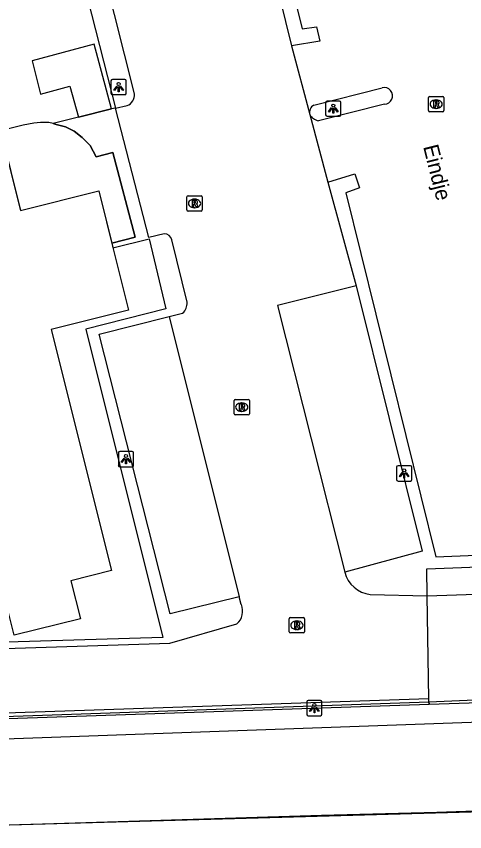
# Model space of a CAD drawing. Extents: x 160806 to 161707, y 383697 to 384148.
# Drawn here: x 160956.3 to 160985.6, y 383697.5 to 383750.7 of the extents above; entities that cross this region are included whole.
import ezdxf

# ---------------------------------------------------------------- set-up
doc = ezdxf.new("R2010")
doc.units = 0
for name, color, linetype in [('IMGEO_Dek', 7, 'Continuous'), ('IMGEO_Hek', 7, 'Continuous'), ('IMGEO_Lichtpunt', 7, 'Continuous'), ('IMGEO_Muur', 7, 'Continuous'), ('IMGEO_Openbare_ruimte_label', 7, 'Continuous'), ('IMGEO_Pand', 7, 'Continuous'), ('IMGEO_Pand_overbouw', 7, 'Continuous'), ('IMGEO_Parkeervlak_gesloten', 7, 'Continuous'), ('IMGEO_Parkeervlak_open', 7, 'Continuous'), ('IMGEO_Rijbaan_lokaal_gesloten', 7, 'Continuous'), ('IMGEO_Rioolput', 7, 'Continuous'), ('IMGEO_Spoorbaan_halfverhard', 7, 'Continuous'), ('IMGEO_Struiken', 7, 'Continuous'), ('IMGEO_Voetpad_gesloten', 7, 'Continuous'), ('IMGEO_Voetpad_op_trap', 7, 'Continuous')]:
    doc.layers.add(name, color=color, linetype=linetype)

msp = doc.modelspace()

# ---------------------------------------------------------------- linework, layer by layer
at = {"layer": 'IMGEO_Dek'}
for points in [[(160918.048, 383703.574), (160983.268, 383705.804), (160983.265, 383705.961), (161017.778, 383707.453), (161017.526, 383714.059), (161017.47, 383715.97), (161042.245, 383716.936), (161047.689, 383726.041), (161047.527, 383726.542), (161047.162, 383727.994), (161034.181, 383780.096)], [(160959.395, 383758.125), (160962.801, 383744.714), (160962.544, 383744.668), (160960.397, 383744.126), (160958.73, 383743.717), (160958.926, 383743.665), (160959.552, 383743.495), (160960.1, 383743.212), (160960.626, 383742.816), (160961.142, 383742.274), (160961.54, 383741.548), (160962.624, 383741.824), (160964.085, 383736.287), (160962.561, 383735.906), (160962.637, 383735.601), (160965.01, 383736.193), (160966.097, 383731.614), (160960.872, 383730.295), (160965.894, 383710.159), (160949.913, 383709.678)]]:
    msp.add_lwpolyline(points, dxfattribs=at)
at = {"layer": 'IMGEO_Hek'}
msp.add_lwpolyline([(161084.555, 383704.866), (161082.059, 383704.545), (161077.717, 383703.87), (161074.945, 383703.576), (161073.852, 383703.453), (161066.359, 383702.75), (161053.876, 383701.607), (161046.412, 383701.035), (161041.411, 383700.754), (161031.392, 383700.349), (161013.875, 383699.768), (161008.19, 383699.597), (160996.33, 383699.168), (160983.78, 383698.726), (160976.256, 383698.527), (160958.785, 383697.993), (160951.307, 383697.771), (160943.792, 383697.709), (160938.784, 383697.68), (160932.094, 383697.764)], dxfattribs=at)
at = {"layer": 'IMGEO_Lichtpunt'}
for p, q in [((160963.413, 383746.6), (160962.605, 383746.6)), ((160963.413, 383746.6), (160962.605, 383746.6)), ((160962.511, 383746.505), (160962.511, 383745.698)), ((160962.511, 383746.505), (160962.511, 383745.698)), ((160963.507, 383745.698), (160963.507, 383746.505)), ((160963.507, 383745.698), (160963.507, 383746.505)), ((160962.605, 383745.604), (160963.413, 383745.604)), ((160962.605, 383745.604), (160963.413, 383745.604)), ((160976.521, 383745.093), (160976.521, 383744.286)), ((160976.521, 383745.093), (160976.521, 383744.286)), ((160977.423, 383745.188), (160976.615, 383745.188)), ((160977.423, 383745.188), (160976.615, 383745.188)), ((160977.517, 383744.286), (160977.517, 383745.093)), ((160977.517, 383744.286), (160977.517, 383745.093)), ((160976.615, 383744.192), (160977.423, 383744.192)), ((160976.615, 383744.192), (160977.423, 383744.192)), ((160962.99, 383722.203), (160962.99, 383721.396)), ((160962.99, 383722.203), (160962.99, 383721.396)), ((160963.892, 383722.298), (160963.084, 383722.298)), ((160963.892, 383722.298), (160963.084, 383722.298)), ((160963.986, 383721.396), (160963.986, 383722.203)), ((160963.986, 383721.396), (160963.986, 383722.203)), ((160963.084, 383721.302), (160963.892, 383721.302)), ((160963.084, 383721.302), (160963.892, 383721.302)), ((160981.148, 383721.27), (160981.148, 383720.463)), ((160981.148, 383721.27), (160981.148, 383720.463)), ((160982.05, 383721.365), (160981.242, 383721.365)), ((160982.05, 383721.365), (160981.242, 383721.365)), ((160982.144, 383720.463), (160982.144, 383721.27)), ((160982.144, 383720.463), (160982.144, 383721.27)), ((160981.242, 383720.369), (160982.05, 383720.369)), ((160981.242, 383720.369), (160982.05, 383720.369)), ((160975.284, 383705.946), (160975.284, 383705.139)), ((160975.284, 383705.946), (160975.284, 383705.139)), ((160976.186, 383706.041), (160975.378, 383706.041)), ((160976.186, 383706.041), (160975.378, 383706.041)), ((160976.28, 383705.139), (160976.28, 383705.946)), ((160976.28, 383705.139), (160976.28, 383705.946)), ((160975.378, 383705.045), (160976.186, 383705.045)), ((160975.378, 383705.045), (160976.186, 383705.045))]:
    msp.add_line(p, q, dxfattribs=at)
for points in [[(160962.885, 383746.169), (160962.924, 383746.141), (160962.736, 383745.879), (160962.698, 383745.906), (160962.885, 383746.169)], [(160962.987, 383746.121), (160963.034, 383746.121), (160963.034, 383745.799), (160962.987, 383745.799), (160962.987, 383746.121)], [(160963.097, 383746.141), (160963.135, 383746.168), (160963.322, 383745.906), (160963.283, 383745.878), (160963.097, 383746.141)], [(160976.895, 383744.757), (160976.934, 383744.729), (160976.746, 383744.467), (160976.708, 383744.494), (160976.895, 383744.757)], [(160976.997, 383744.709), (160977.044, 383744.709), (160977.044, 383744.387), (160976.997, 383744.387), (160976.997, 383744.709)], [(160977.107, 383744.729), (160977.145, 383744.756), (160977.332, 383744.494), (160977.293, 383744.466), (160977.107, 383744.729)], [(160963.364, 383721.867), (160963.403, 383721.839), (160963.215, 383721.577), (160963.177, 383721.604), (160963.364, 383721.867)], [(160963.466, 383721.819), (160963.513, 383721.819), (160963.513, 383721.497), (160963.466, 383721.497), (160963.466, 383721.819)], [(160963.576, 383721.839), (160963.614, 383721.866), (160963.801, 383721.604), (160963.762, 383721.576), (160963.576, 383721.839)], [(160981.522, 383720.934), (160981.561, 383720.906), (160981.373, 383720.644), (160981.335, 383720.671), (160981.522, 383720.934)], [(160981.624, 383720.886), (160981.671, 383720.886), (160981.671, 383720.564), (160981.624, 383720.564), (160981.624, 383720.886)], [(160981.734, 383720.906), (160981.772, 383720.933), (160981.959, 383720.671), (160981.92, 383720.643), (160981.734, 383720.906)], [(160975.658, 383705.61), (160975.697, 383705.582), (160975.509, 383705.32), (160975.471, 383705.347), (160975.658, 383705.61)], [(160975.76, 383705.562), (160975.807, 383705.562), (160975.807, 383705.24), (160975.76, 383705.24), (160975.76, 383705.562)], [(160975.87, 383705.582), (160975.908, 383705.609), (160976.095, 383705.347), (160976.056, 383705.319), (160975.87, 383705.582)]]:
    msp.add_lwpolyline(points, dxfattribs=at)
for centre in [(160963.01, 383746.303), (160977.02, 383744.891), (160963.489, 383722.001), (160981.647, 383721.068), (160975.783, 383705.744)]:
    msp.add_circle(centre, 0.0994, dxfattribs=at)
for centre, start, end in [((160962.605, 383746.505), 90, 180), ((160962.605, 383746.505), 90, 180), ((160963.413, 383746.505), 0, 90), ((160963.413, 383746.505), 0, 90), ((160962.605, 383745.698), 180, 270), ((160962.605, 383745.698), 180, 270), ((160963.413, 383745.698), 270, 0), ((160963.413, 383745.698), 270, 360), ((160976.615, 383745.093), 90, 180), ((160976.615, 383745.093), 90, 180), ((160977.423, 383745.093), 0, 90), ((160977.423, 383745.093), 0, 90), ((160976.615, 383744.286), 180, 270), ((160976.615, 383744.286), 180, 270), ((160977.423, 383744.286), 270, 0), ((160977.423, 383744.286), 270, 360), ((160963.084, 383722.203), 90, 180), ((160963.084, 383722.203), 90, 180), ((160963.892, 383722.203), 0, 90), ((160963.892, 383722.203), 0, 90), ((160963.084, 383721.396), 180, 270), ((160963.084, 383721.396), 180, 270), ((160963.892, 383721.396), 270, 0), ((160963.892, 383721.396), 270, 360), ((160981.242, 383721.27), 90, 180), ((160981.242, 383721.27), 90, 180), ((160982.05, 383721.27), 0, 90), ((160982.05, 383721.27), 0, 90), ((160981.242, 383720.463), 180, 270), ((160981.242, 383720.463), 180, 270), ((160982.05, 383720.463), 270, 0), ((160982.05, 383720.463), 270, 360), ((160975.378, 383705.946), 90, 180), ((160975.378, 383705.946), 90, 180), ((160976.186, 383705.946), 0, 90), ((160976.186, 383705.946), 0, 90), ((160975.378, 383705.139), 180, 270), ((160975.378, 383705.139), 180, 270), ((160976.186, 383705.139), 270, 0), ((160976.186, 383705.139), 270, 360)]:
    msp.add_arc(centre, 0.0946, start, end, dxfattribs=at)
at = {"layer": 'IMGEO_Muur'}
msp.add_lwpolyline([(161017.812, 383705.748), (161000, 383705.11), (160925.136, 383702.425), (160925.233, 383698.384), (160918.04, 383698.804)], dxfattribs=at)
at = {"layer": 'IMGEO_Pand'}
msp.add_lwpolyline([(160955.357, 383743.043), (160956.607, 383738.039), (160961.709, 383739.314), (160961.795, 383738.969), (160962.631, 383735.625), (160963.657, 383731.523), (160958.607, 383730.26), (160962.541, 383714.522), (160959.898, 383713.862), (160960.518, 383711.382), (160956.184, 383710.298), (160955.552, 383712.828), (160949.497, 383711.315), (160949.382, 383711.774), (160941.019, 383745.231), (160944.207, 383746.028), (160948.634, 383747.134), (160953.999, 383748.475), (160955.308, 383743.237), (160955.357, 383743.043)], dxfattribs=at)
at = {"layer": 'IMGEO_Pand_overbouw'}
msp.add_lwpolyline([(160962.624, 383741.824), (160961.54, 383741.548), (160961.142, 383742.274), (160960.626, 383742.816), (160960.1, 383743.212), (160959.552, 383743.495), (160958.926, 383743.665), (160958.73, 383743.717), (160958.447, 383743.791), (160957.901, 383743.793), (160957.479, 383743.751), (160956.788, 383743.617), (160955.308, 383743.237), (160956.607, 383738.039), (160961.709, 383739.314), (160962.561, 383735.906), (160964.085, 383736.287)], close=True, dxfattribs=at)
at = {"layer": 'IMGEO_Parkeervlak_gesloten'}
for points in [[(160975.751, 383744.92), (160980.215, 383746.059)], [(160980.353, 383744.983), (160976.055, 383743.904)]]:
    msp.add_lwpolyline(points, dxfattribs=at)
for centre, radius, start, end in [((160980.338, 383745.528), 0.545, 271.5281, 103.0888), ((160976.002, 383744.442), 0.539, 117.6932, 194.3122), ((160976.192, 383744.711), 0.818, 209.3963, 260.3797)]:
    msp.add_arc(centre, radius, start, end, dxfattribs=at)
at = {"layer": 'IMGEO_Parkeervlak_open'}
msp.add_lwpolyline([(160945.396, 383704.652), (160983.265, 383705.961), (160983.268, 383705.804), (161017.796, 383706.954)], dxfattribs=at)
at = {"layer": 'IMGEO_Rijbaan_lokaal_gesloten'}
for points in [[(160971.205, 383761.352), (160974.285, 383748.798)], [(160964.044, 383745.648), (160960.762, 383758.727)], [(160974.285, 383748.798), (160975.479, 383744.309)], [(160962.801, 383744.714), (160963.569, 383744.888)], [(160965.987, 383736.523), (160964.99, 383736.27), (160962.801, 383744.714)], [(160975.479, 383744.309), (160976.667, 383739.892)], [(160976.667, 383739.892), (160978.516, 383733.118)], [(160967.481, 383732.043), (160966.476, 383736.126)], [(160978.516, 383733.118), (160973.367, 383731.844), (160977.776, 383714.424)], [(160966.311, 383731.117), (160967.184, 383731.336)], [(160966.311, 383731.117), (160970.868, 383712.807)], [(160983.144, 383712.87), (160990.144, 383713.112), (161017.526, 383714.059)], [(160983.265, 383705.961), (161017.778, 383707.453), (161017.526, 383714.059)], [(160971.017, 383712.305), (160970.868, 383712.807)], [(160979.43, 383712.971), (160983.144, 383712.87)], [(160983.262, 383706.136), (160983.144, 383712.87)], [(160948.844, 383709.215), (160966.347, 383709.785), (160970.734, 383711.048)], [(160983.262, 383706.136), (160945.346, 383704.857)], [(160983.265, 383705.961), (160983.262, 383706.136)]]:
    msp.add_lwpolyline(points, dxfattribs=at)
for centre, radius, start, end in [((160963.267, 383745.605), 0.778, 292.8384, 3.1509), ((160965.985, 383736.021), 0.502, 12.0773, 89.7791), ((160966.624, 383731.987), 0.859, 310.6885, 3.7384), ((160979.625, 383714.861), 1.9, 193.3042, 264.0987), ((160969.999, 383711.874), 1.106, 311.6762, 22.9479)]:
    msp.add_arc(centre, radius, start, end, dxfattribs=at)
at = {"layer": 'IMGEO_Rioolput'}
for p, q in [((160983.231, 383744.559), (160983.231, 383745.411)), ((160983.306, 383745.485), (160984.158, 383745.485)), ((160983.719, 383745.265), (160983.744, 383745.265)), ((160984.232, 383745.411), (160984.232, 383744.559)), ((160984.158, 383744.485), (160983.306, 383744.485)), ((160983.742, 383744.705), (160983.717, 383744.705)), ((160967.463, 383738.073), (160967.463, 383738.925)), ((160967.538, 383738.999), (160968.39, 383738.999)), ((160967.951, 383738.779), (160967.976, 383738.779)), ((160968.464, 383738.925), (160968.464, 383738.073)), ((160967.974, 383738.219), (160967.949, 383738.219)), ((160968.39, 383737.999), (160967.538, 383737.999)), ((160970.544, 383724.77), (160970.544, 383725.622)), ((160970.619, 383725.696), (160971.471, 383725.696)), ((160971.032, 383725.476), (160971.057, 383725.476)), ((160971.545, 383725.622), (160971.545, 383724.77)), ((160971.055, 383724.916), (160971.03, 383724.916)), ((160971.471, 383724.696), (160970.619, 383724.696)), ((160974.217, 383711.453), (160975.069, 383711.453)), ((160974.142, 383710.527), (160974.142, 383711.379)), ((160974.63, 383711.233), (160974.655, 383711.233)), ((160975.143, 383711.379), (160975.143, 383710.527)), ((160975.069, 383710.453), (160974.217, 383710.453)), ((160974.653, 383710.673), (160974.628, 383710.673))]:
    msp.add_line(p, q, dxfattribs=at)
for points in [[(160983.231, 383744.559), (160983.231, 383745.411)], [(160983.306, 383745.485), (160984.158, 383745.485)], [(160983.82, 383745.183), (160983.568, 383745.185), (160983.568, 383744.785)], [(160983.746, 383745.104), (160983.692, 383745.104), (160983.692, 383745.023)], [(160983.692, 383745.023), (160983.744, 383745.023)], [(160984.232, 383745.411), (160984.232, 383744.559)], [(160984.158, 383744.485), (160983.306, 383744.485)], [(160983.568, 383744.785), (160983.692, 383744.785), (160983.692, 383744.947), (160983.703, 383744.947)], [(160983.75, 383744.918), (160983.821, 383744.785), (160983.961, 383744.785), (160983.896, 383744.911)], [(160967.463, 383738.073), (160967.463, 383738.925)], [(160967.538, 383738.999), (160968.39, 383738.999)], [(160968.052, 383738.697), (160967.8, 383738.699), (160967.8, 383738.299)], [(160967.978, 383738.618), (160967.924, 383738.618), (160967.924, 383738.537)], [(160968.464, 383738.925), (160968.464, 383738.073)], [(160967.8, 383738.299), (160967.924, 383738.299), (160967.924, 383738.461), (160967.935, 383738.461)], [(160967.924, 383738.537), (160967.976, 383738.537)], [(160967.982, 383738.432), (160968.053, 383738.299), (160968.193, 383738.299), (160968.128, 383738.425)], [(160968.39, 383737.999), (160967.538, 383737.999)], [(160970.544, 383724.77), (160970.544, 383725.622)], [(160970.619, 383725.696), (160971.471, 383725.696)], [(160971.133, 383725.394), (160970.881, 383725.396), (160970.881, 383724.996)], [(160971.059, 383725.315), (160971.005, 383725.315), (160971.005, 383725.234)], [(160971.545, 383725.622), (160971.545, 383724.77)], [(160970.881, 383724.996), (160971.005, 383724.996), (160971.005, 383725.158), (160971.016, 383725.158)], [(160971.005, 383725.234), (160971.057, 383725.234)], [(160971.063, 383725.129), (160971.134, 383724.996), (160971.274, 383724.996), (160971.209, 383725.122)], [(160971.471, 383724.696), (160970.619, 383724.696)], [(160974.217, 383711.453), (160975.069, 383711.453)], [(160974.142, 383710.527), (160974.142, 383711.379)], [(160974.731, 383711.151), (160974.479, 383711.153), (160974.479, 383710.753)], [(160974.479, 383710.753), (160974.603, 383710.753), (160974.603, 383710.915), (160974.614, 383710.915)], [(160974.657, 383711.072), (160974.603, 383711.072), (160974.603, 383710.991)], [(160974.603, 383710.991), (160974.655, 383710.991)], [(160974.661, 383710.886), (160974.732, 383710.753), (160974.872, 383710.753), (160974.807, 383710.879)], [(160975.143, 383711.379), (160975.143, 383710.527)], [(160975.069, 383710.453), (160974.217, 383710.453)]]:
    msp.add_lwpolyline(points, dxfattribs=at)
for centre, radius, start, end in [((160983.308, 383745.409), 0.0765, 91.552, 178.448), ((160983.308, 383745.409), 0.0765, 91.552, 178.448), ((160983.728, 383745.212), 0.19, 274.7715, 282.9687), ((160983.752, 383745.008), 0.0964, 77.0061, 93.1865), ((160983.766, 383745.065), 0.0378, 276.6634, 79.6772), ((160983.819, 383745.073), 0.109, 350.3612, 89.416), ((160983.817, 383745.073), 0.112, 277.5842, 350.9817), ((160984.156, 383745.409), 0.0765, 1.552, 88.448), ((160984.156, 383745.409), 0.0765, 1.552, 88.448), ((160983.308, 383744.561), 0.0765, 181.552, 268.448), ((160983.308, 383744.561), 0.0765, 181.552, 268.448), ((160983.702, 383744.894), 0.0533, 26.0293, 88.6989), ((160983.801, 383744.858), 0.108, 29.5134, 73.7905), ((160984.156, 383744.561), 0.0765, 271.552, 358.448), ((160984.156, 383744.561), 0.0765, 271.552, 358.448), ((160967.54, 383738.923), 0.0765, 91.552, 178.448), ((160967.54, 383738.923), 0.0765, 91.552, 178.448), ((160967.984, 383738.522), 0.0964, 77.0061, 93.1865), ((160967.998, 383738.579), 0.0378, 276.6634, 79.6772), ((160968.051, 383738.587), 0.109, 350.3612, 89.416), ((160968.388, 383738.923), 0.0765, 1.552, 88.448), ((160968.388, 383738.923), 0.0765, 1.552, 88.448), ((160967.54, 383738.075), 0.0765, 181.552, 268.448), ((160967.54, 383738.075), 0.0765, 181.552, 268.448), ((160967.934, 383738.408), 0.0533, 26.0293, 88.6989), ((160967.96, 383738.726), 0.19, 274.7715, 282.9687), ((160968.049, 383738.587), 0.112, 277.5842, 350.9817), ((160968.033, 383738.372), 0.108, 29.5134, 73.7905), ((160968.388, 383738.075), 0.0765, 271.552, 358.448), ((160968.388, 383738.075), 0.0765, 271.552, 358.448), ((160970.621, 383725.62), 0.0765, 91.552, 178.448), ((160970.621, 383725.62), 0.0765, 91.552, 178.448), ((160971.065, 383725.219), 0.0964, 77.0061, 93.1865), ((160971.079, 383725.276), 0.0378, 276.6634, 79.6772), ((160971.132, 383725.284), 0.109, 350.3612, 89.416), ((160971.13, 383725.284), 0.112, 277.5842, 350.9817), ((160971.469, 383725.62), 0.0765, 1.552, 88.448), ((160971.469, 383725.62), 0.0765, 1.552, 88.448), ((160970.621, 383724.772), 0.0765, 181.552, 268.448), ((160970.621, 383724.772), 0.0765, 181.552, 268.448), ((160971.015, 383725.105), 0.0533, 26.0293, 88.6989), ((160971.041, 383725.423), 0.19, 274.7715, 282.9687), ((160971.114, 383725.069), 0.108, 29.5134, 73.7905), ((160971.469, 383724.772), 0.0765, 271.552, 358.448), ((160971.469, 383724.772), 0.0765, 271.552, 358.448), ((160974.219, 383711.377), 0.0765, 91.552, 178.448), ((160974.219, 383711.377), 0.0765, 91.552, 178.448), ((160975.067, 383711.377), 0.0765, 1.552, 88.448), ((160975.067, 383711.377), 0.0765, 1.552, 88.448), ((160974.613, 383710.862), 0.0533, 26.0293, 88.6989), ((160974.639, 383711.18), 0.19, 274.7715, 282.9687), ((160974.663, 383710.976), 0.0964, 77.0061, 93.1865), ((160974.677, 383711.033), 0.0378, 276.6634, 79.6772), ((160974.73, 383711.041), 0.109, 350.3612, 89.416), ((160974.728, 383711.041), 0.112, 277.5842, 350.9817), ((160974.712, 383710.826), 0.108, 29.5134, 73.7905), ((160974.219, 383710.529), 0.0765, 181.552, 268.448), ((160974.219, 383710.529), 0.0765, 181.552, 268.448), ((160975.067, 383710.529), 0.0765, 271.552, 358.448), ((160975.067, 383710.529), 0.0765, 271.552, 358.448)]:
    msp.add_arc(centre, radius, start, end, dxfattribs=at)
for centre, major_axis, ratio, start_param, end_param in [((160983.718, 383744.985), (-0.387, 0.002), 0.722429, 4.712389, 7.853982), ((160983.743, 383744.985), (-0.39, 0.002), 0.717154, 1.570796, 4.712389), ((160967.95, 383738.499), (-0.387, 0.002), 0.722429, 4.712389, 7.853982), ((160967.975, 383738.499), (-0.39, 0.002), 0.717154, 1.570796, 4.712389), ((160971.031, 383725.196), (-0.387, 0.002), 0.722429, 4.712389, 7.853982), ((160971.056, 383725.196), (-0.39, 0.002), 0.717154, 1.570796, 4.712389), ((160974.629, 383710.953), (-0.387, 0.002), 0.722429, 4.712389, 7.853982), ((160974.654, 383710.953), (-0.39, 0.002), 0.717154, 1.570796, 4.712389)]:
    msp.add_ellipse(centre, major_axis=major_axis, ratio=ratio, start_param=start_param, end_param=end_param, dxfattribs=at)
at = {"layer": 'IMGEO_Spoorbaan_halfverhard'}
msp.add_lwpolyline([(161073.852, 383703.453), (161066.359, 383702.75), (161050.171, 383701.028), (161040.034, 383700.432), (161009.181, 383699.4), (160949.68, 383697.713), (160939.829, 383697.51), (160932.571, 383697.47), (160925.335, 383698.113), (160925.233, 383698.384)], dxfattribs=at)
at = {"layer": 'IMGEO_Struiken'}
msp.add_lwpolyline([(161017.796, 383706.954), (161017.812, 383705.748), (161000, 383705.11), (160925.136, 383702.425), (160925.233, 383698.384)], dxfattribs=at)
at = {"layer": 'IMGEO_Voetpad_gesloten'}
for points in [[(160994.095, 383747.26), (160992.821, 383747.959), (160991.495, 383747.627), (160990.71, 383747.495), (160990.251, 383747.813), (160985.51, 383766.882), (160971.605, 383763.473), (160974.981, 383749.905), (160975.93, 383750.029), (160976.135, 383749.107), (160974.285, 383748.798)], [(160959.333, 383758.368), (160959.395, 383758.125), (160962.801, 383744.714)], [(160962.801, 383744.714), (160962.544, 383744.668), (160960.397, 383744.126), (160958.73, 383743.717), (160958.926, 383743.665), (160959.552, 383743.495), (160960.1, 383743.212), (160960.626, 383742.816), (160961.142, 383742.274), (160961.54, 383741.548), (160962.624, 383741.824), (160964.085, 383736.287), (160962.561, 383735.906), (160962.637, 383735.601), (160965.01, 383736.193), (160966.097, 383731.614), (160960.872, 383730.295), (160965.894, 383710.159), (160949.913, 383709.678)], [(160976.667, 383739.892), (160978.422, 383740.436), (160978.72, 383739.522), (160977.847, 383739.202), (160983.71, 383715.431), (161017.446, 383716.817)], [(160978.516, 383733.118), (160982.823, 383715.796), (160977.776, 383714.424)], [(160970.868, 383712.807), (160966.369, 383711.688), (160961.742, 383729.971), (160966.311, 383731.117)], [(160983.144, 383712.87), (160983.113, 383714.631), (161017.47, 383715.97)], [(160918.048, 383703.574), (160983.268, 383705.804), (160983.265, 383705.961)]]:
    msp.add_lwpolyline(points, dxfattribs=at)
at = {"layer": 'IMGEO_Voetpad_op_trap'}
msp.add_lwpolyline([(160961.422, 383748.893), (160957.364, 383747.817), (160957.919, 383745.642), (160959.828, 383746.161), (160960.397, 383744.126), (160962.544, 383744.668), (160961.422, 383748.893)], dxfattribs=at)

# ---------------------------------------------------------------- texts
at = {"layer": 'IMGEO_Openbare_ruimte_label'}
msp.add_text('Eindje', height=1, rotation=284.064, dxfattribs=at).set_placement((160982.877, 383742.213))

doc.saveas('drawing.dxf')
